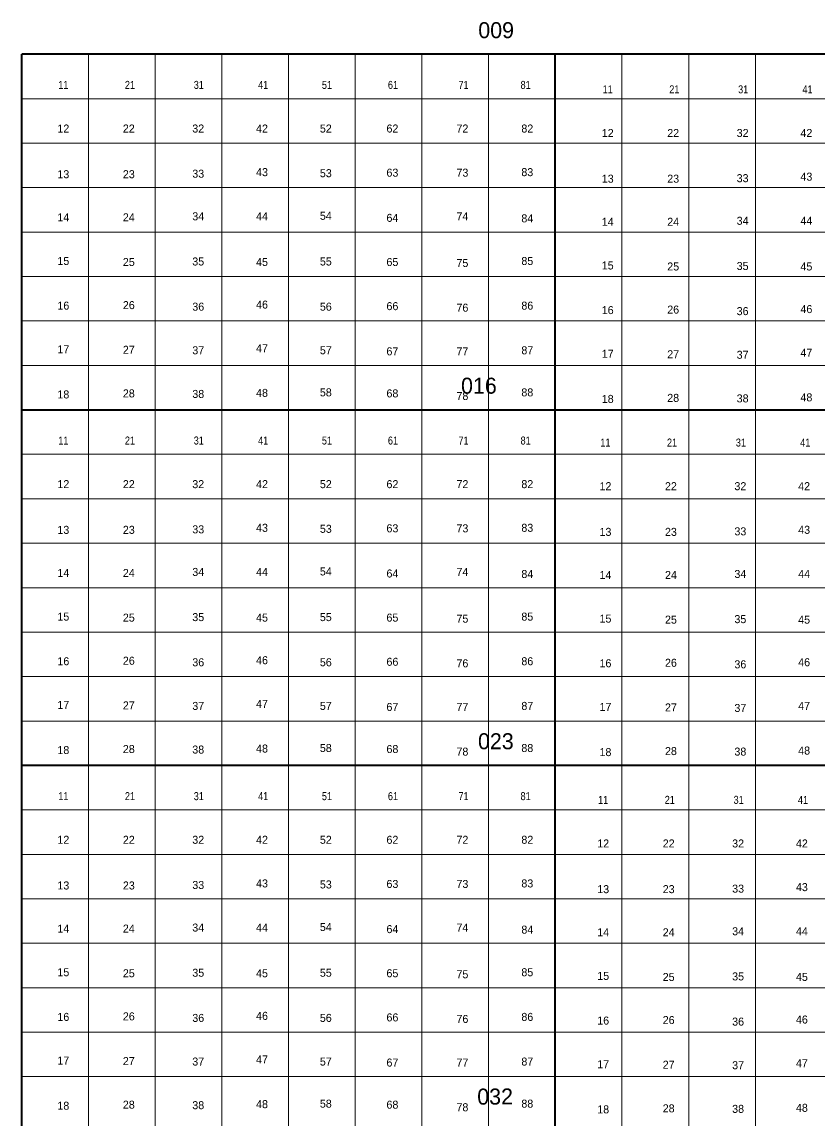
# Model space of a CAD drawing. Extents: x 639000 to 672000, y 222000 to 252000.
# Drawn here: x 639000 to 643472, y 242017 to 248182 of the extents above; entities that cross this region are included whole.
import ezdxf
from ezdxf.enums import TextEntityAlignment as Align

# ---------------------------------------------------------------- set-up
doc = ezdxf.new("R2010")
doc.units = 0
doc.header["$LTSCALE"] = 18
doc.layers.add('1', color=7, linetype='Continuous', lineweight=13)
doc.layers.add('2', color=7, linetype='Continuous')
doc.layers.add('29', color=7, linetype='Continuous')

msp = doc.modelspace()

# ---------------------------------------------------------------- linework, layer by layer
at = {"layer": '1', "lineweight": 35}
for p, q in [((639000, 234000), (639000, 248000)), ((660000, 248000), (639000, 248000)), ((642000, 224000), (642000, 248000)), ((639000, 246000), (663000, 246000)), ((666000, 244000), (639000, 244000))]:
    msp.add_line(p, q, dxfattribs=at)
at = {"layer": '1'}
for p, q in [((639375, 234000), (639375, 248000)), ((639750, 234000), (639750, 248000)), ((640125, 234000), (640125, 248000)), ((640500, 234000), (640500, 248000)), ((640875, 234000), (640875, 248000)), ((641250, 234000), (641250, 248000)), ((641625, 234000), (641625, 248000)), ((642375, 224000), (642375, 248000)), ((642750, 224000), (642750, 248000)), ((643125, 224000), (643125, 248000)), ((660000, 247750), (639000, 247750)), ((660000, 247500), (639000, 247500)), ((660000, 247250), (639000, 247250)), ((660000, 247000), (639000, 247000)), ((660000, 246750), (639000, 246750)), ((660000, 246500), (639000, 246500)), ((660000, 246250), (639000, 246250)), ((663000, 245750), (639000, 245750)), ((663000, 245500), (639000, 245500)), ((663000, 245250), (639000, 245250)), ((663000, 245000), (639000, 245000)), ((663000, 244750), (639000, 244750)), ((663000, 244500), (639000, 244500)), ((663000, 244250), (639000, 244250)), ((639000, 243750), (666000, 243750)), ((639000, 243500), (666000, 243500)), ((639000, 243250), (666000, 243250)), ((639000, 243000), (666000, 243000)), ((639000, 242750), (666000, 242750)), ((639000, 242500), (666000, 242500)), ((639000, 242250), (666000, 242250))]:
    msp.add_line(p, q, dxfattribs=at)

# ---------------------------------------------------------------- texts
at = {"layer": '2'}
for s, p in [('009', (641667.23, 248090.34)), ('016', (641570.28, 246090.88)), ('023', (641665.62, 244091.41))]:
    msp.add_text(s, height=90, dxfattribs=at).set_placement(p, align=Align.CENTER)
msp.add_text('032', height=90, rotation=0.36, dxfattribs=at).set_placement((641661.59, 242093.25), align=Align.CENTER)
at = {"layer": '29', "width": 0.85}
for s, p in [('11', (639232.94, 247805.06)), ('21', (639607.55, 247805.06)), ('31', (639994.85, 247805.06)), ('41', (640356.75, 247805.06)), ('51', (640715.48, 247805.06)), ('61', (641086.91, 247805.06)), ('71', (641483.74, 247805.06)), ('81', (641832.95, 247805.06)), ('11', (642294.65, 247779.89)), ('21', (642669.26, 247779.89)), ('31', (643056.56, 247779.89)), ('41', (643418.46, 247779.89)), ('11', (639232.94, 245805.06)), ('21', (639607.55, 245805.06)), ('31', (639994.85, 245805.06)), ('41', (640356.75, 245805.06)), ('51', (640715.48, 245805.06)), ('61', (641086.91, 245805.06)), ('71', (641483.74, 245805.06)), ('81', (641832.95, 245805.06)), ('11', (642281.95, 245793.67)), ('21', (642656.56, 245793.67)), ('31', (643043.86, 245793.67)), ('41', (643405.77, 245793.67)), ('11', (639232.94, 243805.06)), ('21', (639607.55, 243805.06)), ('31', (639994.85, 243805.06)), ('41', (640356.75, 243805.06)), ('51', (640715.48, 243805.06)), ('61', (641086.91, 243805.06)), ('71', (641483.74, 243805.06)), ('81', (641832.95, 243805.06)), ('11', (642269.26, 243784.35)), ('21', (642643.86, 243784.35)), ('31', (643031.16, 243784.35)), ('41', (643393.07, 243784.35))]:
    msp.add_text(s, height=45, dxfattribs=at).set_placement(p, align=Align.CENTER)
at = {"layer": '29'}
for s, p in [('12', (639232.94, 247559.67)), ('22', (639601.2, 247559.67)), ('32', (639991.67, 247559.67)), ('42', (640350.4, 247559.67)), ('52', (640709.13, 247559.67)), ('62', (641083.74, 247559.67)), ('72', (641477.39, 247559.67)), ('82', (641842.47, 247559.67)), ('12', (642294.65, 247534.5)), ('22', (642662.91, 247534.5)), ('32', (643053.38, 247534.5)), ('42', (643412.11, 247534.5)), ('13', (639232.94, 247302.73)), ('23', (639601.2, 247302.73)), ('33', (639991.67, 247305.62)), ('43', (640350.4, 247314.28)), ('53', (640709.13, 247308.51)), ('63', (641083.74, 247311.39)), ('73', (641477.39, 247311.39)), ('83', (641842.47, 247314.28)), ('13', (642294.65, 247277.56)), ('23', (642662.91, 247277.56)), ('33', (643053.38, 247280.44)), ('43', (643412.11, 247289.11)), ('14', (639232.94, 247060.23)), ('24', (639601.2, 247060.23)), ('34', (639991.67, 247066)), ('44', (640350.4, 247066)), ('54', (640709.13, 247068.89)), ('64', (641083.74, 247057.34)), ('74', (641477.39, 247066)), ('84', (641842.47, 247054.45)), ('14', (642294.65, 247035.05)), ('24', (642662.91, 247035.05)), ('34', (643053.38, 247040.83)), ('44', (643412.11, 247040.83)), ('15', (639232.94, 246814.84)), ('25', (639601.2, 246809.06)), ('35', (639991.67, 246811.95)), ('45', (640350.4, 246809.06)), ('55', (640709.13, 246811.95)), ('65', (641083.74, 246809.06)), ('75', (641477.39, 246803.29)), ('85', (641842.47, 246814.84)), ('15', (642294.65, 246789.66)), ('25', (642662.91, 246783.89)), ('35', (643053.38, 246786.78)), ('45', (643412.11, 246783.89)), ('16', (639232.94, 246563.67)), ('26', (639601.2, 246566.56)), ('36', (639991.67, 246557.9)), ('46', (640350.4, 246569.45)), ('56', (640709.13, 246557.9)), ('66', (641083.74, 246560.79)), ('76', (641477.39, 246552.12)), ('86', (641842.47, 246563.67)), ('16', (642294.65, 246538.5)), ('26', (642662.91, 246541.39)), ('46', (643412.11, 246544.27)), ('36', (643053.38, 246532.73)), ('17', (639232.94, 246318.28)), ('27', (639601.2, 246315.39)), ('37', (639991.67, 246312.51)), ('47', (640350.4, 246324.05)), ('57', (640709.13, 246312.51)), ('67', (641083.74, 246306.73)), ('77', (641477.39, 246306.73)), ('87', (641842.47, 246312.51)), ('17', (642294.65, 246293.11)), ('47', (643412.11, 246298.88)), ('27', (642662.91, 246290.22)), ('37', (643053.38, 246287.33)), ('18', (639232.94, 246064.23)), ('28', (639601.2, 246070)), ('38', (639991.67, 246067.12)), ('48', (640350.4, 246072.89)), ('58', (640709.13, 246075.78)), ('68', (641083.74, 246070)), ('78', (641477.39, 246055.57)), ('88', (641842.47, 246075.78)), ('28', (642662.91, 246044.83)), ('48', (643412.11, 246047.72)), ('18', (642294.65, 246039.06)), ('38', (643053.38, 246041.94)), ('12', (639232.94, 245559.67)), ('22', (639601.2, 245559.67)), ('32', (639991.67, 245559.67)), ('42', (640350.4, 245559.67)), ('52', (640709.13, 245559.67)), ('62', (641083.74, 245559.67)), ('72', (641477.39, 245559.67)), ('82', (641842.47, 245559.67)), ('12', (642281.95, 245548.28)), ('22', (642650.21, 245548.28)), ('32', (643040.68, 245548.28)), ('42', (643399.42, 245548.28)), ('33', (639991.67, 245305.62)), ('43', (640350.4, 245314.28)), ('53', (640709.13, 245308.51)), ('63', (641083.74, 245311.39)), ('73', (641477.39, 245311.39)), ('83', (641842.47, 245314.28)), ('13', (639232.94, 245302.73)), ('23', (639601.2, 245302.73)), ('13', (642281.95, 245291.34)), ('23', (642650.21, 245291.34)), ('33', (643040.69, 245294.22)), ('43', (643399.42, 245302.89)), ('14', (639232.94, 245060.23)), ('24', (639601.2, 245060.23)), ('34', (639991.67, 245066)), ('44', (640350.4, 245066)), ('54', (640709.13, 245068.89)), ('74', (641477.39, 245066)), ('64', (641083.74, 245057.34)), ('84', (641842.47, 245054.45)), ('14', (642281.95, 245048.83)), ('24', (642650.21, 245048.83)), ('34', (643040.69, 245054.61)), ('44', (643399.42, 245054.61)), ('15', (639232.94, 244814.84)), ('35', (639991.67, 244811.95)), ('55', (640709.13, 244811.95)), ('85', (641842.47, 244814.84)), ('25', (639601.2, 244809.06)), ('45', (640350.4, 244809.06)), ('65', (641083.74, 244809.06)), ('75', (641477.39, 244803.29)), ('15', (642281.95, 244803.44)), ('25', (642650.21, 244797.67)), ('35', (643040.69, 244800.56)), ('45', (643399.42, 244797.67)), ('26', (639601.2, 244566.56)), ('46', (640350.4, 244569.45)), ('16', (639232.94, 244563.67)), ('36', (639991.67, 244557.9)), ('56', (640709.13, 244557.9)), ('66', (641083.74, 244560.79)), ('76', (641477.39, 244552.12)), ('86', (641842.47, 244563.67)), ('16', (642281.95, 244552.28)), ('26', (642650.21, 244555.17)), ('36', (643040.69, 244546.51)), ('46', (643399.42, 244558.05)), ('47', (640350.4, 244324.05)), ('17', (639232.94, 244318.28)), ('27', (639601.2, 244315.39)), ('37', (639991.67, 244312.51)), ('57', (640709.13, 244312.51)), ('67', (641083.74, 244306.73)), ('77', (641477.39, 244306.73)), ('87', (641842.47, 244312.51)), ('17', (642281.95, 244306.89)), ('27', (642650.21, 244304)), ('37', (643040.69, 244301.11)), ('47', (643399.42, 244312.66)), ('48', (640350.4, 244072.89)), ('58', (640709.13, 244075.78)), ('88', (641842.47, 244075.78)), ('18', (639232.94, 244064.23)), ('28', (639601.2, 244070)), ('38', (639991.67, 244067.12)), ('68', (641083.74, 244070)), ('78', (641477.39, 244055.57)), ('18', (642281.95, 244052.84)), ('28', (642650.21, 244058.61)), ('38', (643040.68, 244055.72)), ('48', (643399.42, 244061.5)), ('12', (639232.94, 243559.67)), ('22', (639601.2, 243559.67)), ('32', (639991.67, 243559.67)), ('42', (640350.4, 243559.67)), ('52', (640709.13, 243559.67)), ('62', (641083.74, 243559.67)), ('72', (641477.39, 243559.67)), ('82', (641842.47, 243559.67)), ('12', (642269.25, 243538.96)), ('22', (642637.51, 243538.96)), ('32', (643027.99, 243538.96)), ('42', (643386.72, 243538.96)), ('13', (639232.94, 243302.73)), ('23', (639601.2, 243302.73)), ('33', (639991.67, 243305.62)), ('43', (640350.4, 243314.28)), ('53', (640709.13, 243308.51)), ('63', (641083.74, 243311.39)), ('73', (641477.39, 243311.39)), ('83', (641842.47, 243314.28)), ('13', (642269.26, 243282.02)), ('23', (642637.51, 243282.02)), ('33', (643027.99, 243284.91)), ('43', (643386.72, 243293.57)), ('14', (639232.94, 243060.23)), ('24', (639601.2, 243060.23)), ('34', (639991.67, 243066)), ('44', (640350.4, 243066)), ('54', (640709.13, 243068.89)), ('64', (641083.74, 243057.34)), ('74', (641477.39, 243066)), ('84', (641842.47, 243054.45)), ('14', (642269.26, 243039.52)), ('24', (642637.51, 243039.52)), ('34', (643027.99, 243045.29)), ('44', (643386.72, 243045.29)), ('15', (639232.94, 242814.84)), ('25', (639601.2, 242809.06)), ('35', (639991.67, 242811.95)), ('45', (640350.4, 242809.06)), ('55', (640709.13, 242811.95)), ('65', (641083.74, 242809.06)), ('75', (641477.39, 242803.29)), ('85', (641842.47, 242814.84)), ('15', (642269.26, 242794.13)), ('25', (642637.51, 242788.35)), ('35', (643027.99, 242791.24)), ('45', (643386.72, 242788.35)), ('16', (639232.94, 242563.67)), ('26', (639601.2, 242566.56)), ('36', (639991.67, 242557.9)), ('46', (640350.4, 242569.45)), ('56', (640709.13, 242557.9)), ('66', (641083.74, 242560.79)), ('76', (641477.39, 242552.12)), ('86', (641842.47, 242563.67)), ('16', (642269.26, 242542.96)), ('26', (642637.51, 242545.85)), ('36', (643027.99, 242537.19)), ('46', (643386.72, 242548.74)), ('17', (639232.94, 242318.28)), ('27', (639601.2, 242315.39)), ('37', (639991.67, 242312.51)), ('47', (640350.4, 242324.05)), ('57', (640709.13, 242312.51)), ('67', (641083.74, 242306.73)), ('77', (641477.39, 242306.73)), ('87', (641842.47, 242312.51)), ('17', (642269.26, 242297.57)), ('27', (642637.51, 242294.69)), ('37', (643027.99, 242291.8)), ('47', (643386.72, 242303.35)), ('18', (639232.94, 242064.23)), ('28', (639601.2, 242070)), ('38', (639991.67, 242067.12)), ('48', (640350.4, 242072.89)), ('58', (640709.13, 242075.78)), ('68', (641083.74, 242070)), ('78', (641477.39, 242055.57)), ('88', (641842.47, 242075.78)), ('18', (642269.25, 242043.52)), ('28', (642637.51, 242049.3)), ('38', (643027.99, 242046.41)), ('48', (643386.72, 242052.18))]:
    msp.add_text(s, height=45, dxfattribs=at).set_placement(p, align=Align.CENTER)

doc.saveas('drawing.dxf')
